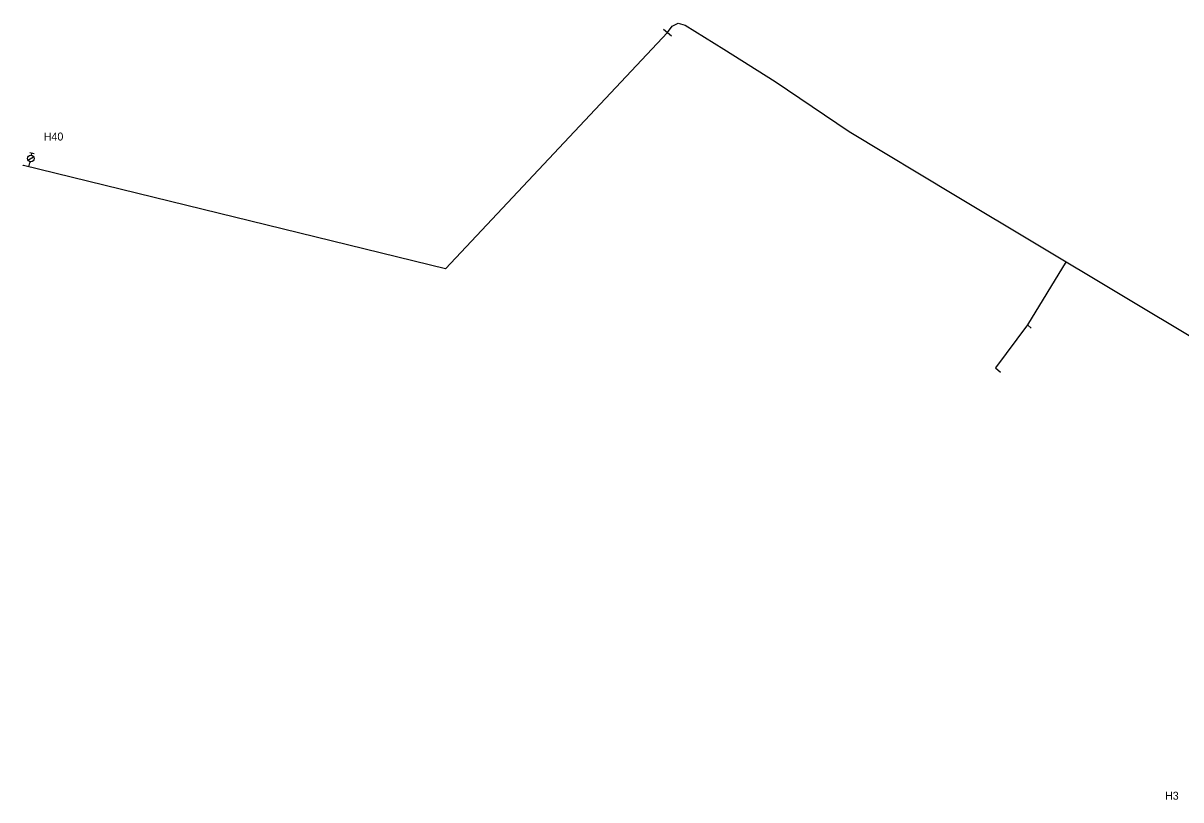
# Model space of a CAD drawing. Extents: x -548873 to -538270, y -1201997 to -1192514.
# Drawn here: x -547773 to -547483.6, y -1201320.7 to -1201126.6 of the extents above; entities that cross this region are included whole.
import ezdxf

# ---------------------------------------------------------------- set-up
doc = ezdxf.new("R2010")
doc.units = 0
for name, color, linetype in [('KN_HRAN_STÁTNÍ', 7, 'Continuous'), ('KN_PARC_Č', 7, 'Continuous'), ('KN_VKP_HRAN_SPORNÁ', 7, 'Continuous'), ('PK_PARC_Čv', 7, 'Continuous'), ('Vrstva 29', 7, 'Continuous')]:
    doc.layers.add(name, color=color, linetype=linetype)

# ---------------------------------------------------------------- blocks, each defined once
blk = doc.blocks.new('147')
at = {"layer": 'KN_HRAN_STÁTNÍ'}
blk.add_line((0, 1.27), (0, -1.27), dxfattribs=at)
blk = doc.blocks.new('160')
at = {"layer": 'KN_HRAN_STÁTNÍ'}
blk.add_circle((0, 0), 0.0458, dxfattribs=at)
blk = doc.blocks.new('133')
at = {"layer": 'KN_HRAN_STÁTNÍ'}
for p, q in [((0.28, 0), (0, 0)), ((0.54, 0.58), (1.7, -0.58)), ((1.94, 0), (2.52, 0)), ((2.52, 0.58), (2.52, -0.58))]:
    blk.add_line(p, q, dxfattribs=at)
blk.add_circle((1.11, 0), 0.825, dxfattribs=at)

msp = doc.modelspace()

# ---------------------------------------------------------------- linework, layer by layer
at = {"layer": 'KN_PARC_Č'}
for points in [[(-547512.26, -1201186.182), (-547521.927, -1201201.935), (-547520.991, -1201202.792)], [(-547521.927, -1201201.935), (-547529.896, -1201212.742), (-547528.629, -1201213.812)]]:
    msp.add_lwpolyline(points, dxfattribs=at)
at = {"layer": 'KN_VKP_HRAN_SPORNÁ'}
for points in [[(-547611.91, -1201128.89), (-547610.7, -1201127.36), (-547609.26, -1201126.57), (-547607.51, -1201127.05), (-547597.84, -1201133.1), (-547584.99, -1201141.19), (-547566.47, -1201153.69), (-547539.9, -1201169.62), (-547478.55, -1201206.38), (-547459.404, -1201220.022), (-547447.389, -1201228.957)], [(-547611.91, -1201128.89), (-547667.397, -1201188.005), (-547772.924, -1201162.123)]]:
    msp.add_lwpolyline(points, dxfattribs=at)
at = {"layer": 'PK_PARC_Čv'}
msp.add_lwpolyline([(-547771.569, -1201162.455), (-547771.336, -1201161.479)], dxfattribs=at)

# ---------------------------------------------------------------- block references
at = {"layer": 'PK_PARC_Čv', "xscale": 0.9999999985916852, "yscale": 0.9999999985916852, "rotation": 76.99999972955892}
msp.add_blockref('133', (-547771.336, -1201161.479), dxfattribs=at)
at = {"layer": 'Vrstva 29'}
for name, p, xscale, yscale, rotation in [('147', (-547611.91, -1201128.89), 1.0000000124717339, 1.0000000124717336, 49.99999868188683), ('160', (-547772.924, -1201162.123), 1.0028916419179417, 1.0028916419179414, 166.30279126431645)]:
    msp.add_blockref(name, p, dxfattribs=dict(at, xscale=xscale, yscale=yscale, rotation=rotation))

# ---------------------------------------------------------------- texts
at = {"layer": 'PK_PARC_Čv'}
for s, p in [('H40', (-547767.836, -1201155.909)), ('H3', (-547487.53, -1201320.67))]:
    msp.add_text(s, height=2, dxfattribs=at).set_placement(p)

doc.saveas('drawing.dxf')
